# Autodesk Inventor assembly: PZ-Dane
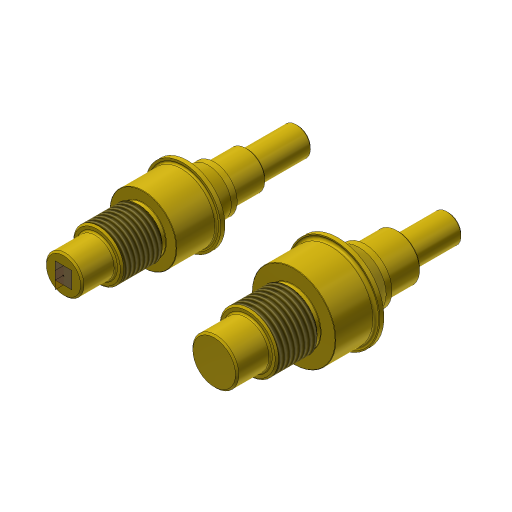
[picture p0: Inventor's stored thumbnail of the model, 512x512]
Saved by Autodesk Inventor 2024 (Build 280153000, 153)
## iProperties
Company: ATC
Created: 2023-03
Part Number: PZ-Dane
Document SubType Name: Assembly
Designer: Andrzej Jaskulski
Checked By: A.J.
Engr Approved By: Andrzej Jaskulski
Mfg Approved By: Andrzej Jaskulski
Authority: A.J.
Title: A.J.: Kurs R2024-MEP
Author: Andrzej Jaskulski
Revision Number: 1/24
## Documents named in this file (3)
- C:\Users\AndJas\Documents\R2024-MEP\Obszar roboczy\PZ\PZ-Dane.iam
- C:\Users\AndJas\Documents\R2024-MEP\Obszar roboczy\PZ\PZ-Dane\Design Accelerator\Wał1.iam
- C:\Users\AndJas\Documents\R2024-MEP\Obszar roboczy\PZ\PZ-Dane\Design Accelerator\Wał2.iam
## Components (2 placed, 1 different names)
1. Wał:1 [sub-assembly] — Odległość OSI, Zestawiający:3, Równoległy:7, Kąt:5
2. Wał:2 [sub-assembly] — Równoległy:5, Równoległy:6, Odległość OSI, Równoległy:8, Kąt:6
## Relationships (8: Flush 4, Mate 2, Angle 2)
- Równoległy:5 [Flush]: Wał:2
- Równoległy:6 [Flush]: Wał:2
- Odległość OSI [Mate]: Wał:1 ↔ Wał:2
- Zestawiający:3 [Mate]: Wał:1
- Równoległy:7 [Flush]: Wał:1
- Kąt:5 [Angle]: Wał:1
- Równoległy:8 [Flush]: Wał:2
- Kąt:6 [Angle]: Wał:2
